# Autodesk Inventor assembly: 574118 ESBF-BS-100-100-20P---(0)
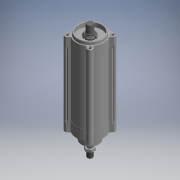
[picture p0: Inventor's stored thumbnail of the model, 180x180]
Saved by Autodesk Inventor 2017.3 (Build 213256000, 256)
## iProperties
Category: PARTsolutions
Company: FESTO
Part Number: 574118 ESBF-BS-100-100-20P---(0)
Catalog Web Link: www.cadenas.de
Description: ESBF-Electro-cylinder
Vendor: FESTO
Document SubType Name: Assembly
Designer: partserver
Manufacturer: FESTO
Mass: 13053 g
Surface Area: 3910.43 cm^2
Volume: 3059.16 cm^3
Density: 4.26685 g/cm^3
Title: 574118 ESBF-BS-100-100-20P
Author: Cadenas PARTsolutions
Comments: Electro-cylinder
PSOL_IDENT_0: {ATYP=ASSISTANT},{DATA=script=$CADENAS_DATA/23d-libs/festo/webfesto.vbb&M_FAMILY=ESBF&M_GROUP=01&M_P
PSOL_IDENT_1: ARTNO=574118&IDCODE1=ESBF-BS-100-100-20P&IDCODE2=&customer_number_cns=&MATES=1&LOD=HI&LOCKERP=0&SING
PSOL_IDENT_2: LEPART=1}
NB: 574118 ESBF-BS-100-100-20P---(0)
NN: ESBF
NT: Electro-cylinder
NBSYN: $TNR. $TYP.---($HUBST.)
LINA: 574118 ESBF-BS-100-100-20P
CATALOG: Festo
TNR: 574118
TYP: ESBF-BS-100-100-20P
ANT: BS
KDM: 100
HUB: 100
SPI: 20P
HUBST: 0
AM: 40
WH: 51
L1: 33
L2: 324
L3: 39.5
L4: 30
L5: 6.1
L7: 68.5
L8: 5
G: 39
G1: 39
VA: 12
VD: 20
ZJ: 375
KK: M20x1.5
MM: 25
B: 70
D1: 50
D2: 24
D3: 100
BG: 17
EE: G1/8
E: 110
RT: M10
SW1: 22
SW2: 30
SW3: 6
TG: 89
CNSMASSEXACT: 13.053
SUPPLIER: FESTO
ARTICLENO: 574118 ESBF-BS-100-100-20P---(0)
BOMINFO: 574118 ESBF-BS-100-100-20P
CREATOR: CADENAS GmbH
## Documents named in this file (6)
- e:\temp\worker_10\temp\exporttempdir_8120_10_GIm1U\format_0\574118 ESBF-BS-100-100-20P---(0).iam
- e:\temp\worker_10\temp\exporttempdir_8120_10_GIm1U\format_0\ESBF-BS-100-100---(ZR_-_-).ipt
- e:\temp\worker_10\temp\exporttempdir_8120_10_GIm1U\format_0\ESBF-BS-100-100-20P---(KS_0).ipt
- e:\temp\worker_10\temp\exporttempdir_8120_10_GIm1U\format_0\DIN-439-B - M20x1_5(F).ipt
- e:\temp\worker_10\temp\exporttempdir_8120_10_GIm1U\format_0\1515746 GUA M28x1_5.ipt
- e:\temp\worker_10\temp\exporttempdir_8120_10_GIm1U\format_0\ESBF-BS-100-ESBF-BS-100---(KSA).ipt
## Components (5 placed, 5 different names)
1. ESBF-BS-100-100---(ZR_-_-):1 — KS_XY@1 <-> ANBAU_XY@2, KS_Z@1 <-> ANBAU_Z@2, KS_YZ@1 <-> ANBAU_YZ@2, GUA_XY@1 <-> ANBAU_XY@4, GUA_Z@1 <-> ANBAU_Z@4, GUA_YZ@1 <-> ANBAU_YZ@4, KSA_XY@1 <-> ANBAU_XY@5, KSA_Z@1 <-> ANBAU_Z@5, KSA_YZ@1 <-> ANBAU_YZ@5
2. ESBF-BS-100-100-20P---(KS_0):1 — KS_XY@1 <-> ANBAU_XY@2, KS_Z@1 <-> ANBAU_Z@2, KS_YZ@1 <-> ANBAU_YZ@2, NUT_XY@2 <-> 2CYL_XY@3, NUT_Z@2 <-> 2CYL_Z@3, NUT_YZ@2 <-> 2CYL_YZ@3
3. DIN-439-B - M20x1_5(F):1 — NUT_XY@2 <-> 2CYL_XY@3, NUT_Z@2 <-> 2CYL_Z@3, NUT_YZ@2 <-> 2CYL_YZ@3
4. 1515746 GUA M28x1_5:1 — GUA_XY@1 <-> ANBAU_XY@4, GUA_Z@1 <-> ANBAU_Z@4, GUA_YZ@1 <-> ANBAU_YZ@4
5. ESBF-BS-100-ESBF-BS-100---(KSA):1 — KSA_XY@1 <-> ANBAU_XY@5, KSA_Z@1 <-> ANBAU_Z@5, KSA_YZ@1 <-> ANBAU_YZ@5
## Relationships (12: Mate 8, Angle 4)
- KS_XY@1 <-> ANBAU_XY@2 [Mate]: ESBF-BS-100-100---(ZR_-_-):1 ↔ ESBF-BS-100-100-20P---(KS_0):1
- KS_Z@1 <-> ANBAU_Z@2 [Mate]: ESBF-BS-100-100---(ZR_-_-):1 ↔ ESBF-BS-100-100-20P---(KS_0):1
- KS_YZ@1 <-> ANBAU_YZ@2 [Angle]: ESBF-BS-100-100---(ZR_-_-):1 ↔ ESBF-BS-100-100-20P---(KS_0):1
- NUT_XY@2 <-> 2CYL_XY@3 [Mate]: ESBF-BS-100-100-20P---(KS_0):1 ↔ DIN-439-B - M20x1_5(F):1
- NUT_Z@2 <-> 2CYL_Z@3 [Mate]: ESBF-BS-100-100-20P---(KS_0):1 ↔ DIN-439-B - M20x1_5(F):1
- NUT_YZ@2 <-> 2CYL_YZ@3 [Angle]: ESBF-BS-100-100-20P---(KS_0):1 ↔ DIN-439-B - M20x1_5(F):1
- GUA_XY@1 <-> ANBAU_XY@4 [Mate]: ESBF-BS-100-100---(ZR_-_-):1 ↔ 1515746 GUA M28x1_5:1
- GUA_Z@1 <-> ANBAU_Z@4 [Mate]: ESBF-BS-100-100---(ZR_-_-):1 ↔ 1515746 GUA M28x1_5:1
- GUA_YZ@1 <-> ANBAU_YZ@4 [Angle]: ESBF-BS-100-100---(ZR_-_-):1 ↔ 1515746 GUA M28x1_5:1
- KSA_XY@1 <-> ANBAU_XY@5 [Mate]: ESBF-BS-100-100---(ZR_-_-):1 ↔ ESBF-BS-100-ESBF-BS-100---(KSA):1
- KSA_Z@1 <-> ANBAU_Z@5 [Mate]: ESBF-BS-100-100---(ZR_-_-):1 ↔ ESBF-BS-100-ESBF-BS-100---(KSA):1
- KSA_YZ@1 <-> ANBAU_YZ@5 [Angle]: ESBF-BS-100-100---(ZR_-_-):1 ↔ ESBF-BS-100-ESBF-BS-100---(KSA):1
